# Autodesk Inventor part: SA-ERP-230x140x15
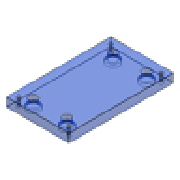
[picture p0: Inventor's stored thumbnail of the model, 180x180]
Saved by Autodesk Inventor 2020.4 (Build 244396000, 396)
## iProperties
Created: 2019-01
Part Number: SA-ERP-230x140x15
Material: S 55 C
Description: Ejector Retainer Plate
Document SubType Name: Modeling
Designer: mel
Standard Revision: 1
Manufacturer: FUTABA
Language: fr-FR
Size Designation: 230x140x15
Categories: <MemberInstance><Categories><Category DisplayName="Moule" InternalName="349578f2-f4d4-4954-8c09-8e99297a61c0" Mnemonic="MOLD"><Category DisplayName="Plaque de m
Density: 7.85 g/cm^3
Appearance: Clear - Blue
IsCustomPart: 1
Author: mel
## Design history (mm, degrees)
sketch "Sketch1"
  geometry: L1 (-70, 115)-(70, 115); L2 (70, 115)-(70, -115); L3 (70, -115)-(-70, -115); L4 (-70, -115)-(-70, 115); 5 further points
  constraints: 8 end point, 2 midpoint, 2 parallel, 1 horizontal, 1 horizontal alignment, 1 perpendicular, 1 vertical alignment
  dimensions: "d84" = 140 distance between parallel lines of L2 L4 (= W_); "d85" = 230 distance between parallel lines of L3 L1 (= L); "d86" = 60 horizontal distance of point (0, 0) point (-60, 105) (= 0.5 x S2_W); "d87" = 105 vertical distance of point (0, 0) point (-60, 105) (= 0.5 x S2_L); "d88" = 53 horizontal distance of point (0, 0) point (-53, 90) (= 0.5 x RP_W); "d89" = 90 vertical distance of point (0, 0) point (-53, 90) (= 0.5 x RP_L)
extrude "Extrusion1" new body sketch "Sketch1" distance "d20" = 15 (= H_); taper "d30" = 0 deg
hole "Hole1" sketch "Sketch1" diameter "d90" = 6.647; stored, may be unused: countersink angle "d94" = 90 deg, drill point angle "d96" = 0 deg; dims "d91" = 6, "d92" = 4, "d93" = 2, "d95" = 15 (= H_)
pattern_linear "Rectangular Pattern1" dims "d99" = 210 (computed from S2_L, Nl), "d102" = 120 (computed from S2_W, Nw)
hole "Hole2" sketch "Sketch1" diameter "d103" = 15 (= RP_d1); stored, may be unused: countersink angle "d107" = 90 deg, drill point angle "d109" = 0 deg; dims "d104" = 6, "d105" = 21 (= RP_d2), "d106" = 4 (= RP_k), "d108" = 15 (= H_)
pattern_linear "Rectangular Pattern2" dims "d112" = 180 (computed from RP_L, Nl), "d115" = 106 (computed from RP_W, Nw)
chamfer "Chamfer1" distance "d116" = 0.5; stored, may be unused: second distance "d117" = 2, angle "d118" = 45 deg
body "Solid1"
other parameters: "L" = 230 [user parameter; used in 1 equation term], "W_" = 140 [user parameter; used in 1 equation term], "H_" = 15 [user parameter; used in 3 equation terms], "RP_k" = 4 [user parameter; used in 1 equation term], "RP_d1" = 15 [user parameter; used in 1 equation term], "RP_d2" = 21 [user parameter; used in 1 equation term], "RP_W" = 106 [user parameter; used in 2 equation terms]
